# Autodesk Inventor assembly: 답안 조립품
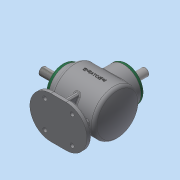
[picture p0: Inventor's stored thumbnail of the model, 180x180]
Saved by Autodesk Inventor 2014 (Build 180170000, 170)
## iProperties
Created: 2023-01
Part Number: 답안 조립품
Document SubType Name: Assembly
Designer: dg
Author: dg
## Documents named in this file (14)
- C:\Users\dg\Desktop\730106V1016\답안 조립품.iam
- C:\Users\dg\Desktop\730106V1016\본체.ipt
- C:\Users\dg\Desktop\730106V1016\서브 축.ipt
- 서브 축.ipt
- C:\Users\dg\Desktop\730106V1016\메인 축.ipt
- 메인 축.ipt
- C:\Users\dg\Desktop\730106V1016\메인 베벨기어.ipt
- C:\Users\dg\Desktop\730106V1016\키 5x5.ipt
- C:\Users\dg\Desktop\730106V1016\키 4x4.ipt
- C:\Users\dg\Desktop\730106V1016\서브 베벨기어.ipt
- C:\Users\dg\Desktop\730106V1016\오일실 17 32 8.ipt
- C:\Users\dg\Desktop\730106V1016\베어링 6203.ipt
- C:\Users\dg\Desktop\730106V1016\커버.ipt
- C:\Users\dg\Desktop\730106V1016\M4.ipt
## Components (8 placed, 1 different names)
1. M4:1
2. M4:2
3. M4:3
4. M4:4
5. M4:5
6. M4:6
7. M4:7
8. M4:8
